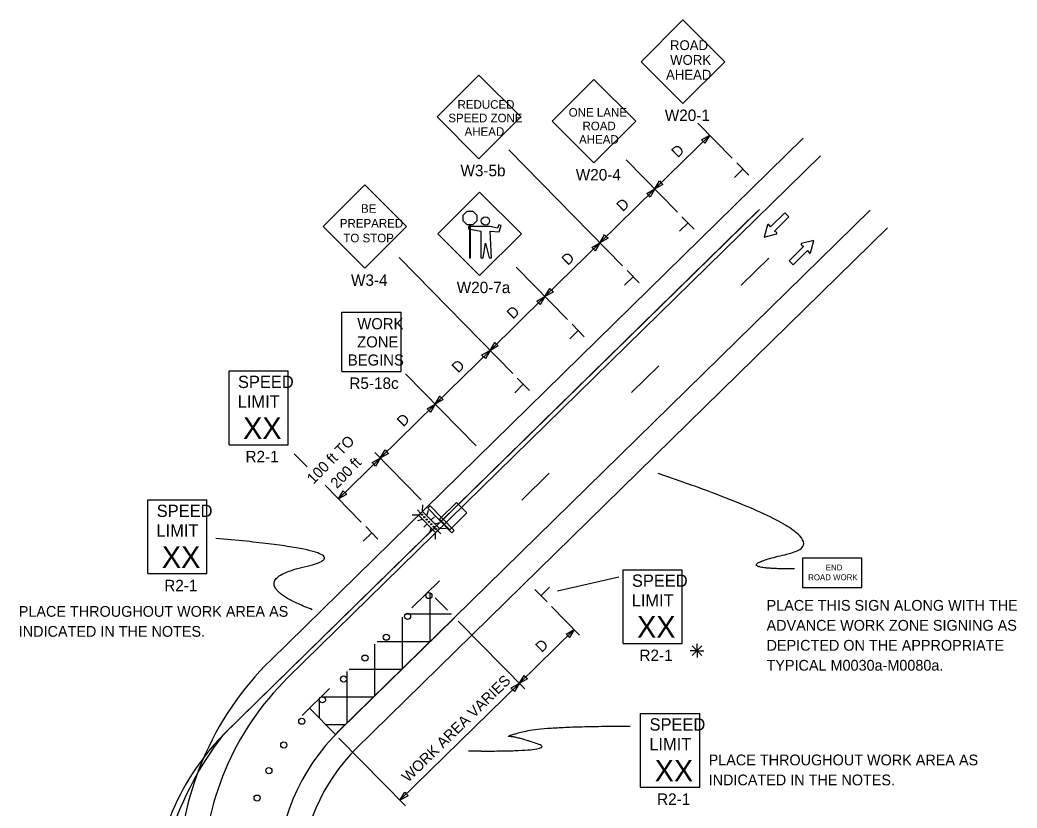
# Model space of a CAD drawing. Extents: x 16735 to 18481, y 5932 to 6923.
# Drawn here: x 16735 to 17383, y 6404 to 6916 of the extents above; entities that cross this region are included whole.
import ezdxf

# ---------------------------------------------------------------- set-up
doc = ezdxf.new("R2010")
doc.units = 0
for name, color, linetype in [('ALI_LEGAL_EX', 7, 'Continuous'), ('MT_SCRATCH_LEVEL_E', 7, 'Continuous'), ('PAVT_EDGE_EX', 7, 'Continuous'), ('TRAFFIC_SIGNS_PR', 7, 'Continuous'), ('TYPICAL_TEXT_DIMEN_PR', 7, 'Continuous')]:
    doc.layers.add(name, color=color, linetype=linetype)

msp = doc.modelspace()

# ---------------------------------------------------------------- linework, layer by layer
at = {"layer": 'ALI_LEGAL_EX'}
msp.add_line((16866.49, 6450.99), (17215.7, 6793.27), dxfattribs=at)
msp.add_arc((17042.09, 6317.17), 220.78, 142.68987, 180.19827, dxfattribs=at)
at = {"layer": 'MT_SCRATCH_LEVEL_E'}
for p, q in [((17232.26, 6791.1), (17222.79, 6781.82)), ((17232.26, 6791.1), (17222.79, 6781.82)), ((17234.87, 6788.43), (17232.26, 6791.1)), ((17234.87, 6788.43), (17232.26, 6791.1)), ((17220.94, 6783.18), (17218.68, 6775.15)), ((17220.94, 6783.18), (17218.68, 6775.15)), ((17222.79, 6781.82), (17221.77, 6783.31)), ((17222.79, 6781.82), (17221.77, 6783.31)), ((17225.41, 6779.15), (17234.87, 6788.43)), ((17225.41, 6779.15), (17234.87, 6788.43)), ((17218.68, 6775.15), (17226.72, 6777.28)), ((17218.68, 6775.15), (17226.72, 6777.28)), ((17226.88, 6778.1), (17225.41, 6779.15)), ((17226.88, 6778.1), (17225.41, 6779.15)), ((17242.92, 6770.15), (17244.39, 6769.1)), ((17242.92, 6770.15), (17244.39, 6769.1)), ((17251.12, 6773.1), (17243.07, 6770.97)), ((17251.12, 6773.1), (17243.07, 6770.97)), ((17248.85, 6765.07), (17251.12, 6773.1)), ((17248.85, 6765.07), (17251.12, 6773.1)), ((17244.39, 6769.1), (17234.92, 6759.82)), ((17244.39, 6769.1), (17234.92, 6759.82)), ((17237.54, 6757.15), (17247.01, 6766.42)), ((17237.54, 6757.15), (17247.01, 6766.42)), ((17247.01, 6766.42), (17248.03, 6764.94)), ((17247.01, 6766.42), (17248.03, 6764.94)), ((17234.92, 6759.82), (17237.54, 6757.15)), ((17234.92, 6759.82), (17237.54, 6757.15))]:
    msp.add_line(p, q, dxfattribs=at)
for centre, start, end in [((17221.39, 6783.04), 34.46189, 164.19881), ((17221.39, 6783.04), 34.46189, 164.19881), ((17226.6, 6777.73), 284.85054, 54.38951), ((17226.6, 6777.73), 284.85054, 54.38951), ((17243.2, 6770.52), 104.85054, 234.38951), ((17243.2, 6770.52), 104.85054, 234.38951), ((17248.4, 6765.21), 214.46189, 344.19881), ((17248.4, 6765.21), 214.46189, 344.19881)]:
    msp.add_arc(centre, 0.463, start, end, dxfattribs=at)
at = {"layer": 'PAVT_EDGE_EX'}
for p, q in [((16897.83, 6500.06), (17244.21, 6839.57)), ((17255.41, 6828.15), (16909.03, 6488.64)), ((16867.78, 6452.26), (17214.45, 6792.05)), ((17287.77, 6792.65), (16941.09, 6452.86)), ((17298.97, 6781.22), (16953.19, 6442.3)), ((17000.67, 6542.05), (17000.67, 6542.05))]:
    msp.add_line(p, q, dxfattribs=at)
for points in [[(17203.89, 6744.04), (17221.74, 6761.54)], [(17132.47, 6674.04), (17150.33, 6691.54)], [(17061.06, 6604.05), (17078.91, 6621.55)], [(16989.64, 6534.05), (17007.49, 6551.55)], [(16918.22, 6464.05), (16936.08, 6481.55)]]:
    msp.add_lwpolyline(points, dxfattribs=at)
for centre, radius, start, end in [((17037.83, 6357.23), 200, 134.42576, 179.99991), ((17037.83, 6357.23), 184, 134.42582, 180.00009), ((17079.73, 6313.2), 226.78, 134.42580555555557, 134.42580833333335), ((16981.31, 6339.5), 160, 134.35623, 180.00012), ((17037.83, 6357.23), 136, 134.35623, 180.00013), ((17079.73, 6313.2), 203.78, 134.42580555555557, 134.42580833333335), ((17037.83, 6357.23), 120, 134.35623, 180.00014), ((17079.73, 6313.2), 180.78, 134.42580555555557, 134.42580833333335), ((17079.73, 6313.2), 180.78, 134.42580555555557, 134.42580833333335), ((17079.73, 6313.2), 180.78, 134.42580555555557, 134.42580833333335), ((17079.73, 6313.2), 180.78, 134.42580555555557, 134.42580833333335)]:
    msp.add_arc(centre, radius, start, end, dxfattribs=at)
at = {"layer": 'TRAFFIC_SIGNS_PR'}
for p, q in [((17165.95, 6916.47), (17138.8, 6889.32)), ((17193.11, 6889.32), (17165.95, 6916.47)), ((17138.8, 6889.32), (17165.95, 6862.17)), ((17165.95, 6862.17), (17193.11, 6889.32)), ((17033.28, 6880.54), (17006.12, 6853.39)), ((17060.43, 6853.39), (17033.28, 6880.54)), ((17108.06, 6877.8), (17080.91, 6850.65)), ((17135.21, 6850.65), (17108.06, 6877.8)), ((17006.12, 6853.39), (17033.28, 6826.23)), ((17033.28, 6826.23), (17060.43, 6853.39)), ((17080.91, 6850.65), (17108.06, 6823.5)), ((17108.06, 6823.5), (17135.21, 6850.65)), ((16959.03, 6809.23), (16931.88, 6782.07)), ((16986.19, 6782.07), (16959.03, 6809.23)), ((17033.67, 6804.52), (17006.52, 6777.37)), ((17060.82, 6777.37), (17033.67, 6804.52)), ((16931.88, 6782.07), (16959.03, 6754.92)), ((16959.03, 6754.92), (16986.19, 6782.07)), ((17006.52, 6777.37), (17033.67, 6750.21)), ((17033.67, 6750.21), (17060.82, 6777.37)), ((16944.16, 6687.89), (16944.16, 6726.29)), ((16944.16, 6726.29), (16982.56, 6726.29)), ((16982.56, 6687.89), (16982.56, 6726.29)), ((16870.75, 6688.16), (16909.15, 6688.16)), ((16870.75, 6640.16), (16870.75, 6688.16)), ((16909.15, 6640.16), (16909.15, 6688.16)), ((16944.16, 6687.89), (16982.56, 6687.89)), ((16870.75, 6640.16), (16909.15, 6640.16)), ((16817.91, 6604.29), (16856.31, 6604.29)), ((16817.91, 6556.29), (16817.91, 6604.29)), ((16856.31, 6556.29), (16856.31, 6604.29)), ((17007.57, 6591.71), (17018.72, 6602.64)), ((17025.43, 6595.79), (17018.72, 6602.64)), ((16995.15, 6595.69), (16993.18, 6597.7)), ((16996.6, 6597.11), (16996.65, 6601.1)), ((17000.23, 6597.45), (16999.35, 6594.31)), ((17014.28, 6584.86), (17025.43, 6595.79)), ((16993.7, 6594.27), (16989.71, 6594.31)), ((16996.47, 6591.45), (16993.31, 6590.64)), ((16996.2, 6594.62), (16996.2, 6594.62)), ((16999.36, 6588.49), (16997.35, 6586.52)), ((16997.72, 6593.07), (16997.72, 6593.07)), ((16999.24, 6591.52), (16999.24, 6591.52)), ((17000.76, 6589.97), (17000.76, 6589.97)), ((17002.26, 6591.34), (17004.28, 6593.31)), ((17008.11, 6589.41), (17004.95, 6588.6)), ((17002.03, 6585.77), (17001.16, 6582.63)), ((17002.28, 6588.42), (17002.28, 6588.42)), ((17003.8, 6586.86), (17003.8, 6586.86)), ((17004.98, 6578.73), (17005.02, 6582.72)), ((17005.33, 6585.31), (17005.33, 6585.31)), ((17006.47, 6584.14), (17008.44, 6582.13)), ((17011.91, 6585.52), (17007.92, 6585.56)), ((16817.91, 6556.29), (16856.31, 6556.29)), ((17126.95, 6558.86), (17165.35, 6558.86)), ((17126.95, 6510.86), (17126.95, 6558.86)), ((17165.35, 6510.86), (17165.35, 6558.86)), ((17126.95, 6510.86), (17165.35, 6510.86)), ((17138.42, 6465.34), (17176.82, 6465.34)), ((17138.42, 6417.34), (17138.42, 6465.34)), ((17176.82, 6417.34), (17176.82, 6465.34)), ((17138.42, 6417.34), (17176.82, 6417.34))]:
    msp.add_line(p, q, dxfattribs=at)
for points in [[(17025.63, 6792), (17029.31, 6792), (17031.9, 6789.4), (17031.9, 6785.73), (17029.31, 6783.13), (17025.63, 6783.13), (17023.03, 6785.73), (17023.03, 6789.4)], [(17040.35, 6782.09), (17026.53, 6782.09), (17026.53, 6780.59), (17034.49, 6779.13), (17034.49, 6761.73), (17035.99, 6761.73), (17037.49, 6771.33), (17039.9, 6761.73), (17041.4, 6761.73), (17040.49, 6779.13), (17046.49, 6778.53), (17047.69, 6782.73), (17046.24, 6783.1), (17045.34, 6781)], [(17027.17, 6783.13), (17027.17, 6761.75), (17027.77, 6761.75), (17027.77, 6783.13)], [(17014.28, 6584.86), (17007.57, 6591.71), (17018.72, 6602.64), (17025.43, 6595.79)], [(16996.6, 6596.78), (17007.6, 6585.57), (17005.02, 6583.05), (16994.03, 6594.27)], [(17000.05, 6598.91), (17015.72, 6582.93), (17017.22, 6584.4), (17001.55, 6600.39)], [(17243.75, 6547.24), (17282.15, 6547.24), (17282.15, 6566.44), (17243.75, 6566.44)]]:
    msp.add_lwpolyline(points, close=True, dxfattribs=at)
for centre, radius in [((17037.47, 6785.7), 2.7), ((16996.2, 6594.63), 0.379), ((16997.72, 6593.07), 0.379), ((16999.24, 6591.52), 0.379), ((17000.76, 6589.97), 0.379), ((17002.28, 6588.42), 0.379), ((17003.8, 6586.86), 0.379), ((17005.31, 6585.33), 0.379), ((17000.67, 6542.05), 2), ((16986.83, 6528.48), 2), ((16972.98, 6514.91), 2), ((16959.14, 6501.34), 2), ((16945.29, 6487.78), 2), ((16931.45, 6474.21), 2), ((16918.06, 6460.27), 2), ((16906.35, 6444.84), 2), ((16896.61, 6428.09), 2), ((16889, 6410.28), 2)]:
    msp.add_circle(centre, radius, dxfattribs=at)
for points in [[(17238.47, 6559.33), (17191.24, 6559.33), (17276.26, 6578.67), (17149.82, 6621.39)], [(16924.83, 6532.81), (16877.6, 6551.16), (16962.62, 6570.51), (16862.12, 6579.17)]]:
    msp.add_open_spline(points, degree=2, dxfattribs=at)
at = {"layer": 'TYPICAL_TEXT_DIMEN_PR'}
for p, q in [((17198.03, 6826.5), (17175.58, 6849.4)), ((17183.32, 6841.5), (17147.62, 6806.5)), ((17178.04, 6838.52), (17183.32, 6841.5)), ((17178.04, 6838.52), (17183.32, 6841.5)), ((17183.32, 6841.5), (17180.24, 6836.28)), ((17183.32, 6841.5), (17180.24, 6836.28)), ((17179.14, 6837.4), (17178.04, 6838.52)), ((17179.14, 6837.4), (17178.04, 6838.52)), ((17180.24, 6836.28), (17179.14, 6837.4)), ((17180.24, 6836.28), (17179.14, 6837.4)), ((17126.61, 6756.5), (17052.68, 6831.93)), ((17162.32, 6791.5), (17128.95, 6825.55)), ((17201, 6823.47), (17208.87, 6815.44)), ((17204.94, 6819.45), (17199.38, 6814)), ((17147.62, 6806.5), (17150.7, 6811.73)), ((17147.62, 6806.5), (17150.7, 6811.73)), ((17152.9, 6809.49), (17147.62, 6806.5)), ((17152.9, 6809.49), (17147.62, 6806.5)), ((17150.7, 6811.73), (17151.8, 6810.61)), ((17150.7, 6811.73), (17151.8, 6810.61)), ((17151.8, 6810.61), (17152.9, 6809.49)), ((17151.8, 6810.61), (17152.9, 6809.49)), ((17147.61, 6806.5), (17111.91, 6771.51)), ((17142.33, 6803.52), (17147.61, 6806.5)), ((17142.33, 6803.52), (17147.61, 6806.5)), ((17143.43, 6802.4), (17142.33, 6803.52)), ((17143.43, 6802.4), (17142.33, 6803.52)), ((17147.61, 6806.5), (17144.53, 6801.28)), ((17147.61, 6806.5), (17144.53, 6801.28)), ((17144.53, 6801.28), (17143.43, 6802.4)), ((17144.53, 6801.28), (17143.43, 6802.4)), ((17169.23, 6784.45), (17163.67, 6779)), ((17165.29, 6788.47), (17173.17, 6780.44)), ((17111.91, 6771.51), (17114.99, 6776.73)), ((17111.91, 6771.51), (17114.99, 6776.73)), ((17114.99, 6776.73), (17116.09, 6775.61)), ((17114.99, 6776.73), (17116.09, 6775.61)), ((17111.91, 6771.5), (17076.2, 6736.51)), ((17106.62, 6768.52), (17111.91, 6771.5)), ((17106.62, 6768.52), (17111.91, 6771.5)), ((17111.91, 6771.5), (17108.82, 6766.28)), ((17111.91, 6771.5), (17108.82, 6766.28)), ((17117.19, 6774.49), (17111.91, 6771.51)), ((17117.19, 6774.49), (17111.91, 6771.51)), ((17116.09, 6775.61), (17117.19, 6774.49)), ((17116.09, 6775.61), (17117.19, 6774.49)), ((17107.72, 6767.4), (17106.62, 6768.52)), ((17107.72, 6767.4), (17106.62, 6768.52)), ((17108.82, 6766.28), (17107.72, 6767.4)), ((17108.82, 6766.28), (17107.72, 6767.4)), ((17055.19, 6686.51), (16981.27, 6761.94)), ((17090.9, 6721.51), (17057.53, 6755.55)), ((17129.58, 6753.47), (17137.46, 6745.44)), ((17133.52, 6749.45), (17127.96, 6744.01)), ((17076.2, 6736.51), (17079.29, 6741.73)), ((17081.49, 6739.49), (17076.2, 6736.51)), ((17079.29, 6741.73), (17080.39, 6740.61)), ((17080.39, 6740.61), (17081.49, 6739.49)), ((17076.2, 6736.51), (17040.49, 6701.51)), ((17070.91, 6733.52), (17076.2, 6736.51)), ((17070.91, 6733.52), (17076.2, 6736.51)), ((17072.01, 6732.4), (17070.91, 6733.52)), ((17072.01, 6732.4), (17070.91, 6733.52)), ((17073.11, 6731.28), (17072.01, 6732.4)), ((17073.11, 6731.28), (17072.01, 6732.4)), ((17076.2, 6736.51), (17073.11, 6731.28)), ((17076.2, 6736.51), (17073.11, 6731.28)), ((17093.87, 6718.47), (17101.75, 6710.44)), ((17097.81, 6714.46), (17092.25, 6709.01)), ((17040.49, 6701.51), (17043.58, 6706.73)), ((17040.49, 6701.51), (17043.58, 6706.73)), ((17043.58, 6706.73), (17044.68, 6705.61)), ((17043.58, 6706.73), (17044.68, 6705.61)), ((17044.68, 6705.61), (17045.78, 6704.49)), ((17044.68, 6705.61), (17045.78, 6704.49)), ((17040.49, 6701.51), (17004.78, 6666.51)), ((17035.21, 6698.52), (17040.49, 6701.51)), ((17035.21, 6698.52), (17040.49, 6701.51)), ((17040.49, 6701.51), (17037.41, 6696.28)), ((17040.49, 6701.51), (17037.41, 6696.28)), ((17045.78, 6704.49), (17040.49, 6701.51)), ((17045.78, 6704.49), (17040.49, 6701.51)), ((17036.31, 6697.4), (17035.21, 6698.52)), ((17036.31, 6697.4), (17035.21, 6698.52)), ((17037.41, 6696.28), (17036.31, 6697.4)), ((17037.41, 6696.28), (17036.31, 6697.4)), ((17031.35, 6639.4), (16985.43, 6686.26)), ((17062.1, 6679.46), (17056.54, 6674.01)), ((17058.17, 6683.47), (17066.04, 6675.44)), ((17004.78, 6666.51), (16969.08, 6631.51)), ((16999.5, 6663.53), (17004.78, 6666.51)), ((16999.5, 6663.53), (17004.78, 6666.51)), ((17004.78, 6666.51), (17001.7, 6661.28)), ((17004.78, 6666.51), (17001.7, 6661.28)), ((17004.78, 6666.51), (17007.87, 6671.73)), ((17004.78, 6666.51), (17007.87, 6671.73)), ((17010.07, 6669.49), (17004.78, 6666.51)), ((17010.07, 6669.49), (17004.78, 6666.51)), ((17007.87, 6671.73), (17008.97, 6670.61)), ((17007.87, 6671.73), (17008.97, 6670.61)), ((17008.97, 6670.61), (17010.07, 6669.49)), ((17008.97, 6670.61), (17010.07, 6669.49)), ((17000.6, 6662.4), (16999.5, 6663.53)), ((17000.6, 6662.4), (16999.5, 6663.53)), ((17001.7, 6661.28), (17000.6, 6662.4)), ((17001.7, 6661.28), (17000.6, 6662.4)), ((16921.51, 6625.7), (16913.05, 6634.32)), ((16995.65, 6604.4), (16965.58, 6635.08)), ((16969.08, 6631.51), (16972.16, 6636.73)), ((16969.08, 6631.51), (16972.16, 6636.73)), ((16974.36, 6634.49), (16969.08, 6631.51)), ((16974.36, 6634.49), (16969.08, 6631.51)), ((16972.16, 6636.73), (16973.26, 6635.61)), ((16972.16, 6636.73), (16973.26, 6635.61)), ((16973.26, 6635.61), (16974.36, 6634.49)), ((16973.26, 6635.61), (16974.36, 6634.49)), ((16969.08, 6631.51), (16941.91, 6604.88)), ((16963.79, 6628.53), (16969.08, 6631.51)), ((16963.79, 6628.53), (16969.08, 6631.51)), ((16964.89, 6627.4), (16963.79, 6628.53)), ((16964.89, 6627.4), (16963.79, 6628.53)), ((16965.99, 6626.28), (16964.89, 6627.4)), ((16965.99, 6626.28), (16964.89, 6627.4)), ((16969.08, 6631.51), (16965.99, 6626.28)), ((16969.08, 6631.51), (16965.99, 6626.28)), ((16956.61, 6589.88), (16933.14, 6613.83)), ((16941.91, 6604.88), (16945, 6610.11)), ((16945, 6610.11), (16946.1, 6608.98)), ((16946.1, 6608.98), (16947.2, 6607.86)), ((16947.2, 6607.86), (16941.91, 6604.88)), ((16963.52, 6582.83), (16957.96, 6577.38)), ((16959.58, 6586.85), (16967.46, 6578.82)), ((17084.43, 6545.05), (17124.15, 6554.32)), ((17001.49, 6512.05), (17001.49, 6544.09)), ((17077.53, 6537.93), (17069.66, 6545.97)), ((17073.6, 6541.95), (17079.16, 6547.4)), ((17012.75, 6532.6), (17004.88, 6540.63)), ((17098.71, 6516.33), (17080.51, 6534.9)), ((16942.75, 6454.47), (17017.51, 6527.75)), ((16983.49, 6494.4), (16983.49, 6528.01)), ((17015.3, 6530), (16985.52, 6530)), ((17063.01, 6481.33), (17019.82, 6525.4)), ((17095.22, 6519.9), (17059.51, 6484.9)), ((17089.93, 6516.92), (17095.22, 6519.9)), ((17095.22, 6519.9), (17092.13, 6514.68)), ((17001.44, 6512), (16967.15, 6512)), ((17091.03, 6515.8), (17089.93, 6516.92)), ((17092.13, 6514.68), (17091.03, 6515.8)), ((16965.49, 6476.76), (16965.49, 6510.37)), ((17175.08, 6506.18), (17170.55, 6506.18)), ((17171.89, 6509.37), (17178.26, 6502.99)), ((17178.26, 6509.37), (17171.89, 6502.99)), ((17175.08, 6506.18), (17175.08, 6510.64)), ((17175.08, 6506.18), (17178.26, 6506.18)), ((17175.08, 6506.18), (17179.56, 6506.18)), ((17175.08, 6506.18), (17175.08, 6501.68)), ((16947.49, 6459.12), (16947.49, 6492.73)), ((16983.08, 6494), (16948.79, 6494)), ((17059.51, 6484.9), (16981.9, 6408.84)), ((17054.22, 6481.92), (17059.51, 6484.9)), ((17059.51, 6484.9), (17056.42, 6479.68)), ((17059.51, 6484.9), (17062.59, 6490.13)), ((17064.79, 6487.89), (17059.51, 6484.9)), ((17062.59, 6490.13), (17063.69, 6489.01)), ((17063.69, 6489.01), (17064.79, 6487.89)), ((17055.32, 6480.8), (17054.22, 6481.92)), ((17056.42, 6479.68), (17055.32, 6480.8)), ((16929.49, 6462.32), (16929.49, 6475.08)), ((16964.71, 6476), (16930.42, 6476)), ((16939.94, 6451.65), (16923.14, 6468.79)), ((16923.14, 6468.79), (16939.94, 6451.65)), ((16946.35, 6458), (16933.72, 6458)), ((16985.4, 6405.27), (16942.21, 6449.33)), ((17034.65, 6440.86), (17026.35, 6440.86)), ((16981.9, 6408.84), (16984.99, 6414.07)), ((16984.99, 6414.07), (16986.09, 6412.94)), ((16987.19, 6411.82), (16981.9, 6408.84)), ((16986.09, 6412.94), (16987.19, 6411.82))]:
    msp.add_line(p, q, dxfattribs=at)
msp.add_arc((17037.83, 6357.23), 136, 134.35623, 136.03218, dxfattribs=at)
msp.add_open_spline([(17034.65, 6440.86), (17085.16, 6440.86), (17057.49, 6450.27), (17049.18, 6450.27), (17076.51, 6457.09), (17131.52, 6457.09)], degree=2, dxfattribs=at)

# ---------------------------------------------------------------- texts
at = {"layer": 'TRAFFIC_SIGNS_PR'}
for s, height, p in [('ROAD', 6.4, (17157.5, 6896.86)), ('WORK', 6.4, (17157.6, 6887.26)), ('AHEAD', 6.4, (17154.91, 6877.65)), ('REDUCED', 5.6, (17019.33, 6858.69)), ('SPEED ZONE', 5.6, (17013.33, 6849.89)), ('ONE LANE', 5.6, (17091.64, 6853.52)), ('W20-1', 7.44, (17154.12, 6850.73)), ('ROAD', 5.6, (17100.59, 6844.72)), ('AHEAD', 5.6, (17023.89, 6841.09)), ('AHEAD', 5.6, (17098.35, 6835.92)), ('W3-5b', 7.44, (17021.23, 6814.79)), ('W20-4', 7.44, (17096.24, 6812.06)), ('BE', 5.6, (16956.53, 6791)), ('PREPARED', 5.6, (16942.77, 6781.4)), ('TO STOP', 5.6, (16945.06, 6771.8)), ('W3-4', 7.44, (16950.04, 6743.48)), ('W20-7a', 7.44, (17018.81, 6738.77)), ('WORK', 7.217, (16954.16, 6715.26)), ('ZONE', 7.217, (16954.04, 6703.45)), ('BEGINS', 7.217, (16947.97, 6691.64)), ('SPEED', 8, (16876.52, 6677.02)), ('R5-18c', 7.44, (16948.97, 6676.45)), ('LIMIT', 8, (16876.36, 6664.22)), ('XX', 14.031, (16879.86, 6643.92)), ('R2-1', 7.44, (16881.43, 6628.72)), ('SPEED', 8, (16823.68, 6593.15)), ('LIMIT', 8, (16823.52, 6580.35)), ('XX', 14.031, (16827.03, 6560.05)), ('END', 3.831, (17258.75, 6558.37)), ('R2-1', 7.44, (16828.59, 6544.85)), ('SPEED', 8, (17132.72, 6547.72)), ('ROAD WORK', 3.831, (17247.36, 6551.99)), ('LIMIT', 8, (17132.55, 6534.92)), ('PLACE THIS SIGN ALONG WITH THE', 7, (17220.3, 6532.17)), ('PLACE THROUGHOUT WORK AREA AS', 7, (16733.97, 6528.23)), ('XX', 14.031, (17136.06, 6514.61)), ('ADVANCE WORK ZONE SIGNING AS', 7, (17220.3, 6519.17)), ('INDICATED IN THE NOTES.', 7, (16733.97, 6515.23)), ('DEPICTED ON THE APPROPRIATE', 7, (17220.3, 6506.17)), ('R2-1', 7.44, (17137.63, 6499.42)), ('TYPICAL M0030a-M0080a.', 7, (17220.3, 6493.17)), ('SPEED', 8, (17144.19, 6454.21)), ('LIMIT', 8, (17144.03, 6441.41)), ('XX', 14.031, (17147.53, 6421.1)), ('PLACE THROUGHOUT WORK AREA AS', 7, (17182.64, 6431.6)), ('INDICATED IN THE NOTES.', 7, (17182.64, 6418.6)), ('R2-1', 7.44, (17149.1, 6405.9))]:
    msp.add_text(s, height=height, dxfattribs=at).set_placement(p)
at = {"layer": 'TYPICAL_TEXT_DIMEN_PR'}
for s, rotation, p in [('D', 44.43273, (17162.53, 6826.4)), ('D', 44.43273, (17126.82, 6791.39)), ('D', 44.43273, (17091.12, 6756.39)), ('D', 44.43273, (17055.42, 6721.39)), ('D', 44.43273, (17019.71, 6686.38)), ('D', 44.43273, (16984, 6651.38)), ('100 ft TO', 45.6, (16925.61, 6614.08)), ('200 ft', 45.6, (16940.93, 6611.15)), ('D', 44.43273, (17074.09, 6504.6)), ('WORK AREA VARIES', 44.42594, (16987.21, 6420.12))]:
    msp.add_text(s, height=7, rotation=rotation, dxfattribs=at).set_placement(p)

doc.saveas('drawing.dxf')
